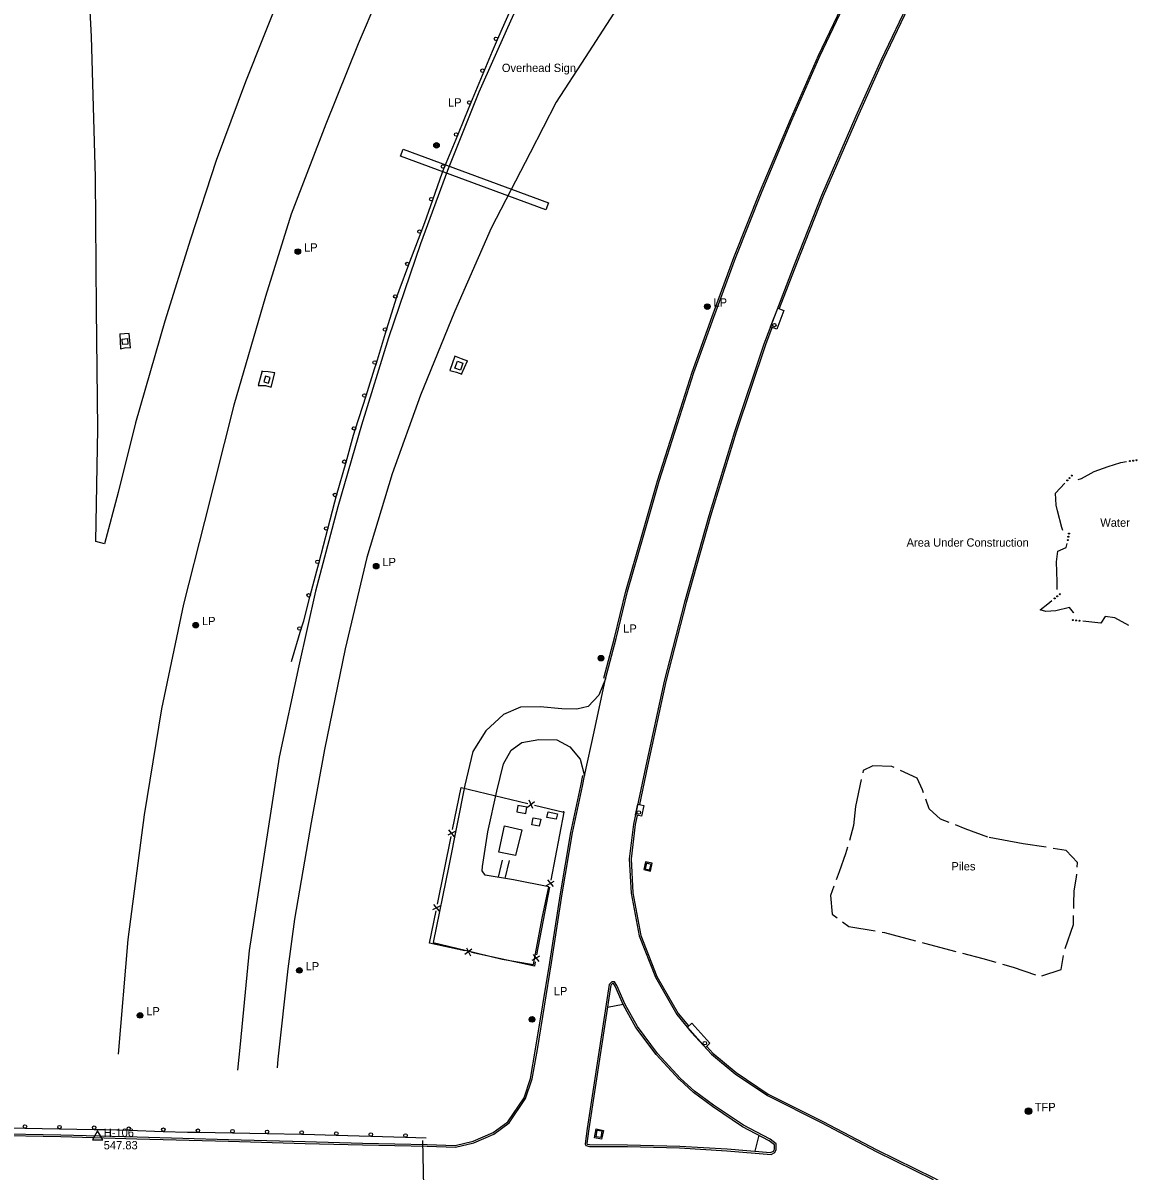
# Model space of a CAD drawing. Extents: x 2402803 to 2427059, y 6985292 to 6997652.
# Drawn here: x 2410720 to 2411364, y 6989618 to 6990282 of the extents above; entities that cross this region are included whole.
import ezdxf

# ---------------------------------------------------------------- set-up
doc = ezdxf.new("R2010")
doc.units = 0
for name, color, linetype in [('p_control ground ctrl', 7, 'Continuous'), ('p_drainage conc drain', 7, 'Continuous'), ('p_drainage water', 7, 'Continuous'), ('p_dtm sidewalk', 7, 'Continuous'), ('p_dtm stock pile', 7, 'Continuous'), ('p_road - paved curb', 7, 'Continuous'), ('p_road bridge end', 7, 'Continuous'), ('p_road guard rails', 7, 'Continuous'), ('p_structure building', 7, 'Continuous'), ('p_structure fence', 7, 'Continuous'), ('p_structure general', 7, 'Continuous'), ('p_structure ruins', 7, 'Continuous'), ('p_structure slab', 7, 'Continuous'), ('p_utility manhole', 7, 'Continuous'), ('V7 LEVEL 31', 7, 'Continuous')]:
    doc.layers.add(name, color=color, linetype=linetype)

msp = doc.modelspace()

# ---------------------------------------------------------------- linework, layer by layer
at = {"layer": 'p_control ground ctrl'}
for p, q in [((2410763.01, 6989641.19), (2410760.01, 6989635.99)), ((2410766.01, 6989635.99), (2410763.01, 6989641.19)), ((2410760.01, 6989635.99), (2410766.01, 6989635.99)), ((2410763.01, 6989637.71), (2410763.01, 6989637.75))]:
    msp.add_line(p, q, dxfattribs=at)
at = {"layer": 'p_drainage conc drain'}
for points in [[(2410776.26, 6990093.35), (2410779.3, 6990094.02), (2410781.97, 6990093.85), (2410781.19, 6990102.24), (2410778.59, 6990102.05), (2410775.82, 6990101.9)], [(2410775.82, 6990101.95), (2410776.26, 6990093.35)], [(2410977.03, 6990086.22), (2410973.39, 6990087.58), (2410969.57, 6990089), (2410966.57, 6990080.74), (2410970.43, 6990079.92), (2410973.5, 6990078.74)], [(2410973.42, 6990078.77), (2410976.81, 6990086.3)], [(2410858.18, 6990080.54), (2410855.88, 6990072.13)], [(2410855.88, 6990072.13), (2410860.13, 6990072.2), (2410863.34, 6990071.09), (2410865.39, 6990079.37)], [(2410865.39, 6990079.37), (2410861.54, 6990080.05), (2410858.09, 6990080.19)]]:
    msp.add_lwpolyline(points, dxfattribs=at)
at = {"layer": 'p_drainage water'}
for points in [[(2411329.78, 6990017.85), (2411331.75, 6990018.3), (2411339.06, 6990022.43), (2411347.15, 6990025.21), (2411354.44, 6990027.71), (2411357.73, 6990028.15)], [(2411320.96, 6989988.37), (2411320.4, 6989989.95), (2411317.77, 6989999.73), (2411317.06, 6990002.94), (2411316.79, 6990009.9), (2411322.16, 6990015.75)], [(2411317.75, 6989954.24), (2411317.62, 6989958.6), (2411317.34, 6989970.12), (2411318.01, 6989976.41), (2411322.95, 6989978.38), (2411323.4, 6989980.8)], [(2411327.23, 6989940.53), (2411327.03, 6989940.95), (2411324.72, 6989943.69), (2411316.86, 6989941.82), (2411311.13, 6989941.52), (2411307.8, 6989942.43), (2411312.28, 6989945.9), (2411314.63, 6989947.79)], [(2411359.11, 6989933.31), (2411350.95, 6989937.87), (2411345.31, 6989938.55), (2411342.97, 6989934.78), (2411332.49, 6989935.88)]]:
    msp.add_lwpolyline(points, dxfattribs=at)
for centre in [(2411359.71, 6990028.41), (2411361.62, 6990028.66), (2411363.52, 6990028.92), (2411323.52, 6990017.22), (2411324.82, 6990018.63), (2411326.11, 6990020.05), (2411324.13, 6989984.66), (2411324.48, 6989986.54), (2411323.77, 6989982.77), (2411319.19, 6989951.44), (2411316.2, 6989949.04), (2411317.69, 6989950.24), (2411326.69, 6989936.49), (2411328.6, 6989936.29), (2411330.5, 6989936.09)]:
    msp.add_circle(centre, 0.3, dxfattribs=at)
at = {"layer": 'p_dtm sidewalk'}
for points in [[(2410996.84, 6989797.74), (2410994.57, 6989787.8)], [(2410998.54, 6989787.13), (2411001.17, 6989797.59)], [(2411057.71, 6989712.78), (2411066.75, 6989714.35)], [(2411145.22, 6989638.61), (2411142.85, 6989629.4)]]:
    msp.add_lwpolyline(points, dxfattribs=at)
at = {"layer": 'p_dtm stock pile'}
for p, q in [((2411204.45, 6989844.35), (2411201.17, 6989828.64)), ((2411298.1, 6989807.13), (2411278.44, 6989810.78)), ((2411311.34, 6989805.13), (2411298.1, 6989807.13))]:
    msp.add_line(p, q, dxfattribs=at)
for points in [[(2411223.37, 6989851.18), (2411222.04, 6989851.78), (2411211.14, 6989852.24), (2411205.54, 6989849.56), (2411205.27, 6989848.26)], [(2411240.47, 6989836.67), (2411239.9, 6989838.31), (2411236.75, 6989845.15), (2411227.01, 6989849.54)], [(2411255.19, 6989819.5), (2411250.27, 6989821.4), (2411243.73, 6989827.32), (2411241.79, 6989832.89)], [(2411201.17, 6989828.64), (2411199.99, 6989817.69), (2411197.54, 6989809.05)], [(2411277.6, 6989810.94), (2411264.57, 6989815.89), (2411258.92, 6989818.07)], [(2411196.45, 6989805.21), (2411195.36, 6989801.38), (2411191.57, 6989790.88), (2411189.9, 6989786.33)], [(2411329.2, 6989793.58), (2411329.37, 6989796.39), (2411322.83, 6989803.32), (2411315.29, 6989804.51)], [(2411327.22, 6989769.73), (2411327.26, 6989772.52), (2411327.44, 6989779.96), (2411328.87, 6989787.9), (2411328.97, 6989789.59)], [(2411188.52, 6989782.58), (2411186.59, 6989777.34), (2411187.64, 6989766.46), (2411190.43, 6989764.36)], [(2411322.23, 6989746.55), (2411327.07, 6989760.46), (2411327.15, 6989765.73)], [(2411193.62, 6989761.95), (2411197.15, 6989759.29), (2411212.53, 6989756.78)], [(2411216.47, 6989756.13), (2411217.78, 6989755.92), (2411235.8, 6989751.07)], [(2411239.65, 6989750.04), (2411240.98, 6989749.68), (2411259, 6989744.98)], [(2411262.87, 6989743.97), (2411274.71, 6989740.88), (2411282.16, 6989738.69)], [(2411308.84, 6989730.75), (2411319.92, 6989734.49), (2411321.39, 6989742.65)], [(2411285.99, 6989737.57), (2411292.15, 6989735.76), (2411305.04, 6989731.49)]]:
    msp.add_lwpolyline(points, dxfattribs=at)
at = {"layer": 'p_road - paved curb'}
for points in [[(2411055.56, 6989902.85), (2411061.71, 6989926.18), (2411068.41, 6989953.32), (2411077.73, 6989986.06), (2411086.73, 6990017.05), (2411097.19, 6990050.24), (2411106.74, 6990079.91), (2411118.3, 6990111.94), (2411130.81, 6990146.14), (2411146.18, 6990184.87), (2411163.44, 6990225.98), (2411179.63, 6990262.96), (2411195.06, 6990295.33), (2411215.61, 6990337.02), (2411233.38, 6990370.35), (2411253.62, 6990408.15), (2411271.85, 6990439.77)], [(2411056.53, 6989902.6), (2411062.68, 6989925.93), (2411069.38, 6989953.06), (2411078.69, 6989985.78), (2411087.69, 6990016.76), (2411098.14, 6990049.94), (2411107.69, 6990079.59), (2411119.24, 6990111.6), (2411131.74, 6990145.78), (2411147.11, 6990184.49), (2411164.36, 6990225.59), (2411180.54, 6990262.54), (2411195.96, 6990294.89), (2411216.5, 6990336.56), (2411234.26, 6990369.88), (2411254.49, 6990407.66), (2411272.72, 6990439.27)], [(2411077.25, 6990435.4), (2411057.34, 6990398.14), (2411035.78, 6990356.65), (2411017.06, 6990317.14), (2410999.92, 6990278.91), (2410983.39, 6990241.64), (2410965.23, 6990196.39), (2410949.69, 6990154), (2410931.16, 6990099.71), (2410915.54, 6990049.24), (2410901.92, 6990001.9), (2410888.93, 6989953.23), (2410879.28, 6989909.97), (2410868.07, 6989857.27), (2410860.56, 6989809.78), (2410850.67, 6989745.47), (2410845.43, 6989691.31), (2410843.94, 6989676.23)], [(2411175.5, 6990432.35), (2411153.06, 6990406.79), (2411132.32, 6990382.11), (2411109.78, 6990353.37), (2411091.4, 6990329.88), (2411067.4, 6990296.93), (2411044.9, 6990261.8), (2411028.04, 6990236.02), (2411013.08, 6990206.73), (2410990.6, 6990163), (2410969.29, 6990114.75), (2410949.59, 6990066.47), (2410933.29, 6990021.03), (2410918.61, 6989972.67), (2410906.2, 6989919.8), (2410894.09, 6989861.77), (2410886.5, 6989819.54), (2410876.93, 6989763.52), (2410872.97, 6989734.86), (2410867.18, 6989682.69), (2410866.75, 6989677.55)], [(2410929.49, 6990428.16), (2410909.06, 6990387.46), (2410888.81, 6990343.61), (2410869.3, 6990300.03), (2410848.5, 6990247.78), (2410831.52, 6990202.16), (2410816.71, 6990156.7), (2410801.85, 6990109.37), (2410784.92, 6990050.57), (2410774.9, 6990010.28), (2410767.05, 6989980.54), (2410762.06, 6989982.02), (2410763.08, 6990047.1), (2410762.3, 6990116.29), (2410761.77, 6990192.49), (2410759.6, 6990273.91), (2410755.83, 6990343.94), (2410750.18, 6990426.24)], [(2410986.02, 6990425.72), (2410957.44, 6990368.44), (2410936.41, 6990323.01), (2410913.55, 6990269.68), (2410894.88, 6990223.25), (2410874.97, 6990171.11), (2410859.98, 6990123.66), (2410841.79, 6990060.78), (2410824.83, 6989993.48), (2410812.6, 6989945.64), (2410799.95, 6989885.19), (2410789.87, 6989823.84), (2410780.49, 6989751.84), (2410774.89, 6989685.51)], [(2411268.5, 6990363.03), (2411266.64, 6990359.6), (2411250.72, 6990329.55), (2411233.68, 6990295.32), (2411216.83, 6990260.01), (2411202.26, 6990227.36), (2411182.37, 6990181.6), (2411166.95, 6990142.54), (2411157.07, 6990116.74)], [(2411232.78, 6990295.76), (2411215.92, 6990260.43), (2411201.34, 6990227.76), (2411181.45, 6990181.98), (2411166.02, 6990142.9), (2411148.08, 6990096.05), (2411131.16, 6990045.36), (2411116.4, 6989996.79), (2411102.18, 6989946.86), (2411090.56, 6989901.16), (2411079.93, 6989852.32), (2411072.75, 6989818.44), (2411070.34, 6989798.46), (2411071.4, 6989778.6), (2411076.06, 6989753.9), (2411085.4, 6989730.02), (2411097.82, 6989708.53), (2411106.32, 6989698.07), (2411117.93, 6989685.46), (2411131.56, 6989674.11), (2411150.15, 6989661.58), (2411181.68, 6989645.78), (2411212.99, 6989629.26), (2411245.91, 6989613.08)], [(2411152.74, 6990105.42), (2411149.02, 6990095.71), (2411132.11, 6990045.06), (2411117.36, 6989996.51), (2411103.15, 6989946.6), (2411091.53, 6989900.93), (2411080.91, 6989852.11), (2411076.21, 6989829.92)], [(2411056.53, 6989902.6), (2411052.7, 6989893.12), (2411046.53, 6989886.55), (2411040.02, 6989884.92), (2411031.4, 6989885.14), (2411018.83, 6989886.39), (2411007.53, 6989886.1), (2410997.59, 6989881.94), (2410987.34, 6989872.55), (2410979.95, 6989860.55), (2410975.37, 6989841.14), (2410965.96, 6989794.46), (2410956.91, 6989750.17), (2410975.49, 6989745.66), (2410996.82, 6989740.51), (2411014.92, 6989737.45), (2411019.94, 6989764.08), (2411023.86, 6989782.23), (2411003.37, 6989786.31), (2410987.01, 6989789.09), (2410985.23, 6989791.47), (2410985.44, 6989793.95), (2410988.64, 6989814.16), (2410993.7, 6989837.51), (2410997.65, 6989853.42), (2411002.03, 6989861.26), (2411008.31, 6989865.66), (2411018.07, 6989867.42), (2411028.38, 6989867.35), (2411036.04, 6989863.22), (2411041.95, 6989856.02), (2411044.45, 6989846.39)], [(2411044.45, 6989846.39), (2411049.99, 6989871.82), (2411056.53, 6989902.6)], [(2410700.85, 6989638.76), (2410741.76, 6989637.84), (2410785.8, 6989636.67), (2410838.64, 6989635.27), (2410882.97, 6989633.95), (2410916.14, 6989633.11), (2410953.43, 6989632.27), (2410969.88, 6989631.82), (2410980.43, 6989634.25), (2410992.13, 6989639.3), (2411000.86, 6989645.74), (2411010.42, 6989659.89), (2411014.16, 6989671.22), (2411017.22, 6989688.32), (2411025.32, 6989738.43), (2411031.55, 6989778.16), (2411037.57, 6989813.49), (2411043.28, 6989840.54), (2411044.45, 6989846.39)], [(2410700.87, 6989639.76), (2410741.78, 6989638.84), (2410785.83, 6989637.67), (2410838.67, 6989636.27), (2410883, 6989634.95), (2410916.16, 6989634.11), (2410953.45, 6989633.27), (2410969.78, 6989632.82), (2410980.12, 6989635.2), (2410991.63, 6989640.17), (2411000.13, 6989646.44), (2411009.51, 6989660.34), (2411013.19, 6989671.47), (2411016.23, 6989688.49), (2411024.33, 6989738.59), (2411030.56, 6989778.32), (2411036.59, 6989813.68), (2411042.3, 6989840.74), (2411043.47, 6989846.59)], [(2411074.85, 6989823.51), (2411073.74, 6989818.28), (2411071.34, 6989798.43), (2411072.4, 6989778.72), (2411077.03, 6989754.18), (2411086.3, 6989730.45), (2411098.65, 6989709.1), (2411104.53, 6989701.86)], [(2411099.98, 6989671.53), (2411086.6, 6989686.01), (2411075.05, 6989701.58), (2411067.9, 6989714.22), (2411063.11, 6989725.26), (2411061.72, 6989727.3), (2411060.23, 6989727.41), (2411058.67, 6989725.88), (2411052.55, 6989685.29)], [(2411099.25, 6989670.85), (2411085.83, 6989685.37), (2411074.21, 6989701.03), (2411067, 6989713.77), (2411062.23, 6989724.78), (2411061.17, 6989726.34), (2411060.61, 6989726.38), (2411059.61, 6989725.4), (2411053.54, 6989685.14)], [(2411115.16, 6989689.94), (2411118.62, 6989686.19), (2411132.16, 6989674.91), (2411150.66, 6989662.45), (2411182.14, 6989646.67), (2411213.44, 6989630.15), (2411246.37, 6989613.97), (2411263.59, 6989604.73)], [(2411052.55, 6989685.29), (2411045.92, 6989642.53), (2411044.79, 6989633.75), (2411045.27, 6989632.71), (2411047.32, 6989632.23), (2411069.3, 6989632.13), (2411099.43, 6989631.37), (2411126.77, 6989629.73), (2411152.26, 6989627.61), (2411154.49, 6989628.74), (2411155.28, 6989630.43), (2411155.18, 6989633.71), (2411151.74, 6989636.32), (2411136.35, 6989644.4), (2411119, 6989656.11), (2411108.07, 6989664.05), (2411099.98, 6989671.53)], [(2411053.54, 6989685.14), (2411046.91, 6989642.39), (2411045.82, 6989633.91), (2411045.97, 6989633.57), (2411047.44, 6989633.23), (2411069.31, 6989633.13), (2411099.47, 6989632.37), (2411126.84, 6989630.73), (2411152.06, 6989628.63), (2411153.73, 6989629.48), (2411154.27, 6989630.64), (2411154.2, 6989633.2), (2411151.2, 6989635.47), (2411135.84, 6989643.54), (2411118.43, 6989655.29), (2411107.43, 6989663.28), (2411099.3, 6989670.8)]]:
    msp.add_lwpolyline(points, dxfattribs=at)
at = {"layer": 'p_road bridge end'}
for points in [[(2411152.03, 6990106.1), (2411156.16, 6990116.88), (2411159.75, 6990115.5), (2411155.62, 6990104.72)], [(2410780.23, 6990099.21), (2410780.5, 6990096.04), (2410777.48, 6990095.78), (2410777.21, 6990098.95)], [(2410969.56, 6990082.19), (2410971.01, 6990086.24), (2410974.16, 6990085.11), (2410972.71, 6990081.06)], [(2410860.16, 6990077.55), (2410859.2, 6990074.16), (2410861.73, 6990073.45), (2410862.69, 6990076.84)], [(2411074.01, 6989823.88), (2411075.3, 6989830), (2411078.71, 6989829.28), (2411077.42, 6989823.16)], [(2411114.36, 6989689.48), (2411103.95, 6989701.16), (2411106.56, 6989703.5), (2411116.97, 6989691.82)]]:
    msp.add_lwpolyline(points, close=True, dxfattribs=at)
msp.add_lwpolyline([(2410950.82, 6989635.61), (2410951.45, 6989608.83), (2410951.52, 6989581.05)], dxfattribs=at)
at = {"layer": 'p_road guard rails'}
for p, q in [((2410994.17, 6990272.18), (2411002.19, 6990290.49)), ((2410978.77, 6990235.34), (2410986.39, 6990253.78)), ((2410963.59, 6990198.35), (2410971.16, 6990216.86)), ((2410942.95, 6990142.08), (2410950.06, 6990160.75)), ((2410930.11, 6990104.24), (2410936.06, 6990123.33)), ((2410924.17, 6990085.14), (2410930.11, 6990104.24)), ((2410912.16, 6990047.01), (2410918.17, 6990066.08)), ((2410901.2, 6990008.57), (2410906.63, 6990027.81)), ((2410891.08, 6989969.91), (2410896.1, 6989989.25)), ((2410875.06, 6989912.49), (2410880.71, 6989931.37)), ((2410701.04, 6989643.02), (2410721.03, 6989642.7)), ((2410721.03, 6989642.7), (2410741.02, 6989642.37)), ((2410741.02, 6989642.37), (2410761.02, 6989642.05)), ((2410781.01, 6989641.52), (2410801, 6989640.91)), ((2410820.99, 6989640.37), (2410840.99, 6989639.99)), ((2410840.99, 6989639.99), (2410860.98, 6989639.62)), ((2410860.98, 6989639.62), (2410880.98, 6989639.25)), ((2410900.97, 6989638.67), (2410920.96, 6989638.07)), ((2410920.96, 6989638.07), (2410940.95, 6989637.48)), ((2410940.95, 6989637.48), (2410952.94, 6989637.12))]:
    msp.add_line(p, q, dxfattribs=at)
for points in [[(2410986.39, 6990253.78), (2410991.24, 6990265.5), (2410994.17, 6990272.18)], [(2410971.16, 6990216.86), (2410975.24, 6990226.81), (2410978.77, 6990235.34)], [(2410956.82, 6990179.55), (2410962.38, 6990195.4), (2410963.59, 6990198.35)], [(2410950.06, 6990160.75), (2410952.19, 6990166.35), (2410956.82, 6990179.55)], [(2410936.06, 6990123.33), (2410937.24, 6990127.11), (2410942.95, 6990142.08)], [(2410918.17, 6990066.08), (2410923.1, 6990081.72), (2410924.17, 6990085.14)], [(2410906.63, 6990027.81), (2410911.03, 6990043.42), (2410912.16, 6990047.01)], [(2410896.1, 6989989.25), (2410900.18, 6990004.94), (2410901.2, 6990008.57)], [(2410885.98, 6989950.59), (2410889.05, 6989962.12), (2410891.08, 6989969.91)], [(2410880.71, 6989931.37), (2410882.14, 6989936.16), (2410885.98, 6989950.59)], [(2410761.02, 6989642.05), (2410767.16, 6989641.95), (2410781.01, 6989641.52)], [(2410801, 6989640.91), (2410814.91, 6989640.48), (2410820.99, 6989640.37)], [(2410880.98, 6989639.25), (2410882.06, 6989639.23), (2410900.97, 6989638.67)]]:
    msp.add_lwpolyline(points, dxfattribs=at)
for centre in [(2410993.25, 6990272.58), (2410985.47, 6990254.16), (2410977.84, 6990235.72), (2410970.24, 6990217.24), (2410962.66, 6990198.73), (2410955.88, 6990179.88), (2410949.12, 6990161.11), (2410942.01, 6990142.44), (2410935.11, 6990123.63), (2410929.16, 6990104.54), (2410923.21, 6990085.44), (2410917.22, 6990066.38), (2410911.21, 6990047.31), (2410905.66, 6990028.08), (2410900.24, 6990008.84), (2410895.13, 6989989.5), (2410890.11, 6989970.17), (2410885.01, 6989950.84), (2410879.75, 6989931.66), (2410721.05, 6989643.7), (2410741.04, 6989643.37), (2410761.03, 6989643.05), (2410781.04, 6989642.52), (2410801.03, 6989641.91), (2410821.01, 6989641.37), (2410841.01, 6989640.99), (2410861, 6989640.62), (2410881, 6989640.25), (2410901, 6989639.67), (2410920.99, 6989639.07), (2410940.98, 6989638.48)]:
    msp.add_circle(centre, 1, dxfattribs=at)
at = {"layer": 'p_structure building'}
msp.add_lwpolyline([(2411008.19, 6989815.2), (2411004.56, 6989800.37), (2410994.88, 6989802.36), (2410998.21, 6989817.56)], close=True, dxfattribs=at)
at = {"layer": 'p_structure fence'}
for p, q in [((2410968.19, 6989815.39), (2410973.13, 6989839.67)), ((2410973.12, 6989839.64), (2411011.77, 6989830.37)), ((2411014.61, 6989827.66), (2411012.44, 6989832.3)), ((2411011.5, 6989828.41), (2411015.55, 6989831.55)), ((2411032.56, 6989825.38), (2411025.04, 6989786.1)), ((2410970, 6989814.41), (2410965.45, 6989812.07)), ((2410969.37, 6989811.27), (2410966.08, 6989815.21)), ((2410959.43, 6989772.27), (2410967.4, 6989811.47)), ((2411022.46, 6989783.13), (2411026.99, 6989785.52)), ((2411023.06, 6989786.28), (2411026.39, 6989782.38)), ((2411024.28, 6989782.17), (2411016.76, 6989742.89)), ((2410960.6, 6989768.16), (2410957.32, 6989772.09)), ((2410961.24, 6989771.29), (2410956.68, 6989768.95)), ((2410979.34, 6989746.32), (2410975.36, 6989743.1)), ((2410976.22, 6989747), (2410978.49, 6989742.41)), ((2411014.18, 6989739.93), (2411018.71, 6989742.32)), ((2411014.79, 6989743.07), (2411018.11, 6989739.17))]:
    msp.add_line(p, q, dxfattribs=at)
for points in [[(2411015.63, 6989829.44), (2411032.56, 6989825.38), (2411032.49, 6989826.07)], [(2410975.22, 6989745.2), (2410954.83, 6989749.67), (2410958.63, 6989768.35)], [(2411016.01, 6989738.97), (2411015.51, 6989736.38), (2410979.12, 6989744.35)]]:
    msp.add_lwpolyline(points, dxfattribs=at)
at = {"layer": 'p_structure general'}
msp.add_lwpolyline([(2411022.16, 6990173.76), (2410938.09, 6990204.65), (2410939.58, 6990208.7), (2411023.65, 6990177.81)], close=True, dxfattribs=at)
for centre in [(2411154.19, 6990107.05), (2411075.88, 6989825.25), (2411114, 6989691.9)]:
    msp.add_circle(centre, 1, dxfattribs=at)
at = {"layer": 'p_structure slab'}
for points in [[(2411005.25, 6989825.67), (2411010.54, 6989824.73), (2411011.17, 6989828.29), (2411005.88, 6989829.23)], [(2411028.11, 6989821.31), (2411022.74, 6989822.4), (2411023.41, 6989825.67), (2411028.78, 6989824.58)], [(2411018.33, 6989817.36), (2411014.08, 6989818.2), (2411014.88, 6989822.24), (2411019.13, 6989821.4)], [(2411079.74, 6989796.71), (2411078.78, 6989792.24), (2411082.57, 6989791.43), (2411083.53, 6989795.9)], [(2411055.36, 6989641.47), (2411054.34, 6989636.36), (2411050.2, 6989637.19), (2411051.22, 6989642.3)]]:
    msp.add_lwpolyline(points, close=True, dxfattribs=at)
at = {"layer": 'p_utility manhole'}
for points in [[(2411082.02, 6989792.07), (2411082.9, 6989795.24), (2411080.38, 6989795.94), (2411079.5, 6989792.77)], [(2411051.2, 6989637.68), (2411051.76, 6989641.52), (2411054.46, 6989641.13), (2411053.9, 6989637.29)]]:
    msp.add_lwpolyline(points, close=True, dxfattribs=at)
for centre, radius in [((2410958.93, 6990210.99), 1.6), ((2410958.93, 6990210.99), 1.3), ((2410958.93, 6990210.99), 1), ((2410958.93, 6990210.99), 0.539), ((2410958.93, 6990210.99), 0.192), ((2410878.78, 6990149.56), 1.6), ((2410878.78, 6990149.56), 1.3), ((2410878.78, 6990149.56), 1), ((2410878.78, 6990149.56), 0.539), ((2410878.78, 6990149.56), 0.192), ((2411115.44, 6990117.76), 1.6), ((2411115.44, 6990117.76), 1.3), ((2411115.44, 6990117.76), 1), ((2411115.44, 6990117.76), 0.539), ((2411115.44, 6990117.76), 0.192), ((2410924.06, 6989967.69), 1.6), ((2410924.06, 6989967.69), 1.3), ((2410924.06, 6989967.69), 1), ((2410924.06, 6989967.69), 0.539), ((2410924.06, 6989967.69), 0.192), ((2410819.77, 6989933.57), 1.6), ((2410819.77, 6989933.57), 1.3), ((2410819.77, 6989933.57), 1), ((2410819.77, 6989933.57), 0.539), ((2410819.77, 6989933.57), 0.192), ((2411053.97, 6989914.48), 1.6), ((2411053.97, 6989914.48), 1.3), ((2411053.97, 6989914.48), 1), ((2411053.97, 6989914.48), 0.539), ((2411053.97, 6989914.48), 0.192), ((2410879.69, 6989733.97), 1.6), ((2410879.69, 6989733.97), 1.3), ((2410879.69, 6989733.97), 1), ((2410879.69, 6989733.97), 0.539), ((2410879.69, 6989733.97), 0.192), ((2410787.59, 6989707.96), 1.6), ((2410787.59, 6989707.96), 1.3), ((2410787.59, 6989707.96), 1), ((2410787.59, 6989707.96), 0.539), ((2410787.59, 6989707.96), 0.192), ((2411014.12, 6989705.62), 1.6), ((2411014.12, 6989705.62), 1.3), ((2411014.12, 6989705.62), 1), ((2411014.12, 6989705.62), 0.539), ((2411014.12, 6989705.62), 0.192), ((2411301.08, 6989652.56), 1.9), ((2411301.08, 6989652.56), 1.44), ((2411301.08, 6989652.56), 0.973), ((2411301.08, 6989652.56), 0.539), ((2411301.08, 6989652.56), 0.192)]:
    msp.add_circle(centre, radius, dxfattribs=at)

# ---------------------------------------------------------------- texts
at = {"layer": 'p_control ground ctrl'}
msp.add_text('  H-106', height=4.8, dxfattribs=at).set_placement((2410763.01, 6989637.71))
at = {"layer": 'p_drainage water'}
msp.add_text('Water', height=4.8, dxfattribs=at).set_placement((2411342.57, 6989990.45))
at = {"layer": 'p_dtm stock pile'}
msp.add_text('Piles', height=4.8, dxfattribs=at).set_placement((2411256.52, 6989791.78))
at = {"layer": 'p_structure general'}
msp.add_text('Overhead Sign', height=4.8, dxfattribs=at).set_placement((2410996.69, 6990253.37))
at = {"layer": 'p_structure ruins'}
msp.add_text('Area Under Construction', height=4.8, dxfattribs=at).set_placement((2411230.63, 6989978.96))
at = {"layer": 'p_utility manhole'}
for s, p in [('  LP', (2410961.99, 6990233.43)), ('  LP', (2410878.78, 6990149.56)), ('  LP', (2411115.44, 6990117.76)), ('  LP', (2410924.06, 6989967.69)), ('  LP', (2410819.77, 6989933.57)), ('  LP', (2411063.27, 6989929.22)), ('  LP', (2410879.69, 6989733.97)), ('  LP', (2411023.13, 6989719.6)), ('  LP', (2410787.59, 6989707.96)), ('  TFP', (2411301.08, 6989652.56))]:
    msp.add_text(s, height=4.8, dxfattribs=at).set_placement(p)
at = {"layer": 'V7 LEVEL 31'}
msp.add_text('  547.83', height=4.8, dxfattribs=at).set_placement((2410763.01, 6989630.51))

doc.saveas('drawing.dxf')
